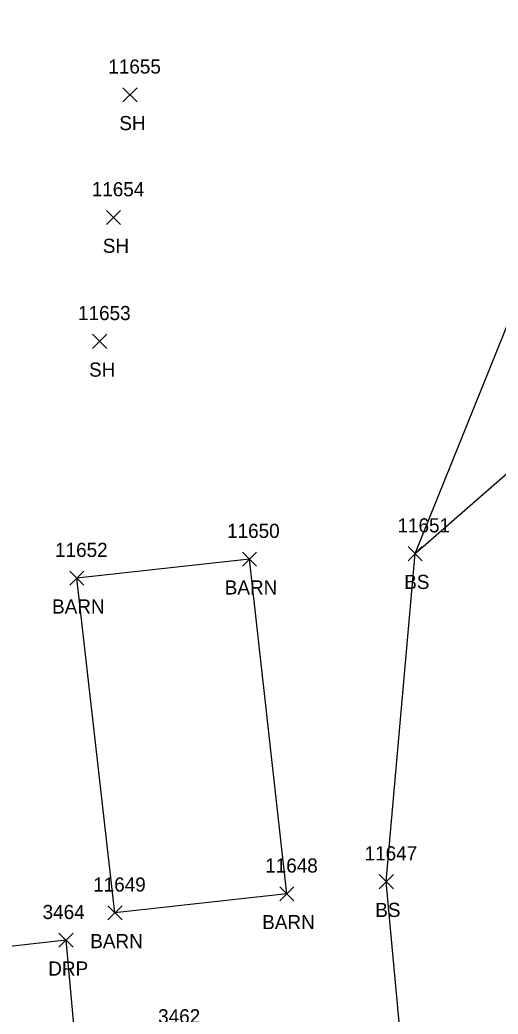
# Model space of a CAD drawing. Extents: x 1769141 to 1770911, y 735471 to 741449.
# Drawn here: x 1770565 to 1770632.6, y 737822.4 to 737963 of the extents above; entities that cross this region are included whole.
import ezdxf

# ---------------------------------------------------------------- set-up
doc = ezdxf.new("R2010")
doc.units = 0
for name, color, linetype in [('L_A', 7, 'Continuous'), ('L_I', 7, 'Continuous'), ('L_TIC', 7, 'Continuous'), ('LBC', 7, 'Continuous'), ('LELB', 7, 'Continuous'), ('LSOGP', 7, 'Continuous'), ('R_A', 7, 'Continuous'), ('R_I', 7, 'Continuous'), ('R_TIC', 7, 'Continuous'), ('RDP', 7, 'Continuous')]:
    doc.layers.add(name, color=color, linetype=linetype)

msp = doc.modelspace()

# ---------------------------------------------------------------- linework, layer by layer
at = {"layer": 'L_TIC'}
for points in [[(1770579.55, 737951.39), (1770581.55, 737953.39)], [(1770581.55, 737951.39), (1770579.55, 737953.39)], [(1770577.21, 737934.04), (1770579.21, 737936.04)], [(1770579.21, 737934.04), (1770577.21, 737936.04)], [(1770575.27, 737916.53), (1770577.27, 737918.53)], [(1770577.27, 737916.53), (1770575.27, 737918.53)], [(1770619.88, 737886.51), (1770621.88, 737888.51)], [(1770621.88, 737886.51), (1770619.88, 737888.51)], [(1770596.44, 737885.73), (1770598.44, 737887.73)], [(1770598.44, 737885.73), (1770596.44, 737887.73)], [(1770572.02, 737883.04), (1770574.02, 737885.04)], [(1770574.02, 737883.04), (1770572.02, 737885.04)], [(1770572.02, 737883.04), (1770574.02, 737885.04)], [(1770574.02, 737883.04), (1770572.02, 737885.04)], [(1770615.8, 737840.13), (1770617.8, 737842.13)], [(1770617.8, 737840.13), (1770615.8, 737842.13)], [(1770601.74, 737838.41), (1770603.74, 737840.41)], [(1770603.74, 737838.41), (1770601.74, 737840.41)], [(1770601.74, 737838.41), (1770603.74, 737840.41)], [(1770603.74, 737838.41), (1770601.74, 737840.41)], [(1770577.42, 737835.72), (1770579.42, 737837.72)], [(1770579.42, 737835.72), (1770577.42, 737837.72)]]:
    msp.add_lwpolyline(points, dxfattribs=at)
at = {"layer": 'LBC'}
for points in [[(1770602.74, 737839.41), (1770597.44, 737886.73), (1770573.02, 737884.04)], [(1770602.74, 737839.41), (1770578.42, 737836.72), (1770573.02, 737884.04)]]:
    msp.add_lwpolyline(points, dxfattribs=at)
at = {"layer": 'LELB'}
msp.add_lwpolyline([(1770619.19, 737815.11), (1770616.8, 737841.13), (1770620.88, 737887.51), (1770640.81, 737936.94), (1770644.87, 737970.57), (1770646.86, 737989.12)], dxfattribs=at)
at = {"layer": 'LSOGP'}
msp.add_lwpolyline([(1770619.19, 737815.11), (1770616.8, 737841.13), (1770620.88, 737887.51), (1770666.8, 737927.57)], dxfattribs=at)
at = {"layer": 'R_TIC'}
for points in [[(1770570.5, 737831.84), (1770572.5, 737833.84)], [(1770572.5, 737831.84), (1770570.5, 737833.84)]]:
    msp.add_lwpolyline(points, dxfattribs=at)
at = {"layer": 'RDP'}
msp.add_lwpolyline([(1770490.29, 737787.37), (1770507.99, 737789.23), (1770543.91, 737792.74), (1770589.63, 737792.76), (1770587.83, 737818.09), (1770572.93, 737817.31), (1770571.5, 737832.84), (1770545.48, 737829.91), (1770540.49, 737829.63), (1770524.84, 737829.21), (1770507.34, 737827.47), (1770508.38, 737805.41), (1770496.94, 737803.45), (1770492.73, 737804.13), (1770488.37, 737807.82)], dxfattribs=at)

# ---------------------------------------------------------------- texts
at = {"layer": 'L_A'}
for s, p in [('SH', (1770579.04, 737947.39)), ('SH', (1770576.7, 737930.04)), ('SH', (1770574.76, 737912.53)), ('BS', (1770619.33, 737882.51)), ('BARN', (1770593.95, 737881.73)), ('BARN', (1770569.53, 737879.04)), ('BARN', (1770569.53, 737879.04)), ('BS', (1770615.24, 737836.13)), ('BARN', (1770599.25, 737834.41)), ('BARN', (1770599.25, 737834.41)), ('BARN', (1770574.93, 737831.72))]:
    msp.add_text(s, height=2, dxfattribs=at).set_placement(p)
at = {"layer": 'L_I'}
for s, p in [('11655', (1770577.48, 737955.39)), ('11654', (1770575.14, 737938.04)), ('11653', (1770573.2, 737920.53)), ('11651', (1770618.38, 737890.51)), ('11650', (1770594.28, 737889.73)), ('11652', (1770569.95, 737887.04)), ('11652', (1770569.95, 737887.04)), ('11647', (1770613.73, 737844.13)), ('11648', (1770599.67, 737842.41)), ('11648', (1770599.67, 737842.41)), ('11649', (1770575.34, 737839.72))]:
    msp.add_text(s, height=2, dxfattribs=at).set_placement(p)
at = {"layer": 'R_A'}
msp.add_text('DRP', height=2, dxfattribs=at).set_placement((1770568.99, 737827.84))
at = {"layer": 'R_I'}
for s, p in [('3464', (1770568.19, 737835.84)), ('3462', (1770584.53, 737821.09))]:
    msp.add_text(s, height=2, dxfattribs=at).set_placement(p)

doc.saveas('drawing.dxf')
